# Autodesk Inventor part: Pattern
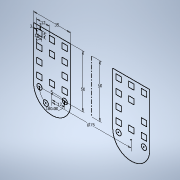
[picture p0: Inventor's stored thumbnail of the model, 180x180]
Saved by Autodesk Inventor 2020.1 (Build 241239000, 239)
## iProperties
Created: 2019-09
Part Number: Pattern
Material: Generic
Document SubType Name: Modeling
Designer: Synergysoft Dell02
Density: 1 g/cm^3
Appearance: Default
Author: Synergysoft Dell02
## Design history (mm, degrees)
sketch "Sketch1"
  geometry: L1 (-17.5, 0)-(-17.5, 50); L2 (-17.5, 50)-(17.5, 50); L3 (17.5, 50)-(17.5, 0); L4 (-14.5, 47)-(-9.5, 47); L5 (-9.5, 47)-(-9.5, 42); L6 (-9.5, 42)-(-14.5, 42); L7 (-14.5, 42)-(-14.5, 47); L8 (-2.5, 47)-(2.5, 47); L9 (2.5, 47)-(2.5, 42); L10 (2.5, 42)-(-2.5, 42); L11 (-2.5, 42)-(-2.5, 47); L12 (9.5, 47)-(14.5, 47); L13 (14.5, 47)-(14.5, 42); L14 (14.5, 42)-(9.5, 42); L15 (9.5, 42)-(9.5, 47); L16 (-14.5, 35)-(-9.5, 35); L17 (-9.5, 35)-(-9.5, 30); L18 (-9.5, 30)-(-14.5, 30); L19 (-14.5, 30)-(-14.5, 35); L20 (-2.5, 35)-(2.5, 35); L21 (2.5, 35)-(2.5, 30); L22 (2.5, 30)-(-2.5, 30); L23 (-2.5, 30)-(-2.5, 35); L24 (9.5, 35)-(14.5, 35); L25 (14.5, 35)-(14.5, 30); L26 (14.5, 30)-(9.5, 30); L27 (9.5, 30)-(9.5, 35); L28 (-14.5, 23)-(-9.5, 23); L29 (-9.5, 23)-(-9.5, 18); L30 (-9.5, 18)-(-14.5, 18); L31 (-14.5, 18)-(-14.5, 23); L32 (-2.5, 23)-(2.5, 23); L33 (2.5, 23)-(2.5, 18); L34 (2.5, 18)-(-2.5, 18); L35 (-2.5, 18)-(-2.5, 23); L36 (9.5, 23)-(14.5, 23); L37 (14.5, 23)-(14.5, 18); L38 (14.5, 18)-(9.5, 18); L39 (9.5, 18)-(9.5, 23); L40 (-14.5, 11)-(-9.5, 11); L41 (-9.5, 11)-(-9.5, 6); L42 (-9.5, 6)-(-14.5, 6); L43 (-14.5, 6)-(-14.5, 11); L44 (-2.5, 11)-(2.5, 11); L45 (2.5, 11)-(2.5, 6); L46 (2.5, 6)-(-2.5, 6); L47 (-2.5, 6)-(-2.5, 11); L48 (9.5, 11)-(14.5, 11); L49 (14.5, 11)-(14.5, 6); L50 (14.5, 6)-(9.5, 6); L51 (9.5, 6)-(9.5, 11); L52 (37.5, 50)-(37.5, 0); L53 (65.5, 23)-(60.5, 23); L54 (57.5, 50)-(57.5, 0); L55 (92.5, 0)-(92.5, 50); L56 (60.5, 18)-(65.5, 18); L57 (65.5, 18)-(65.5, 23); L58 (60.5, 23)-(60.5, 18); L59 (65.5, 11)-(60.5, 11); L60 (65.5, 6)-(65.5, 11); L61 (60.5, 11)-(60.5, 6); L62 (60.5, 6)-(65.5, 6); L63 (65.5, 47)-(60.5, 47); L64 (72.5, 47)-(72.5, 42)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; C1 r 2.5 at (12, 0); C2 r 2.5 at (6, -10.392); C3 r 2.5 at (-6, -10.392); C4 r 2.5 at (-12, 0); C5 r 2.5 at (63, 0); C6 r 2.5 at (69, -10.392); C7 r 2.5 at (87, 0); C8 r 2.5 at (81, -10.392); A1 r 17.5 centre (0, 0) between (-17.5, 0) and (17.5, 0); A2 r 17.5 centre (75, 0) between (57.5, 0) and (92.5, 0); 2 further points
  constraints: 206 end point, 58 symmetric about line, 10 centre point, 4 point on circle, 3 perpendicular, 3 vertical, 2 coincident, 2 horizontal, 2 horizontal alignment, 2 parallel, 2 tangent, 100 other
  dimensions: "d0" = 35 distance of L1.end L2.end; "d1" = 50 distance from line of A1.centre L2; "d2" = 5 distance of L5.end L6.end; "d3" = 5 distance of L4.end L5.end; "d4" = 3 distance between parallel lines of L2 L4; "d5" = 3 distance between parallel lines of L1 L7; "d6" = 5 diameter of C1; "d7" = 12 distance of C1.centre point (0, 0); "d10" = 12 distance of L4.start L8.start; "d13" = 12 distance of L4.start L16.start; "d18" = 180 deg dimension on A1.centre C4.centre C1.centre; "d21" = 75 diameter of point (75, 0) L52; "d22" = 50 distance of L52.start L52.end
